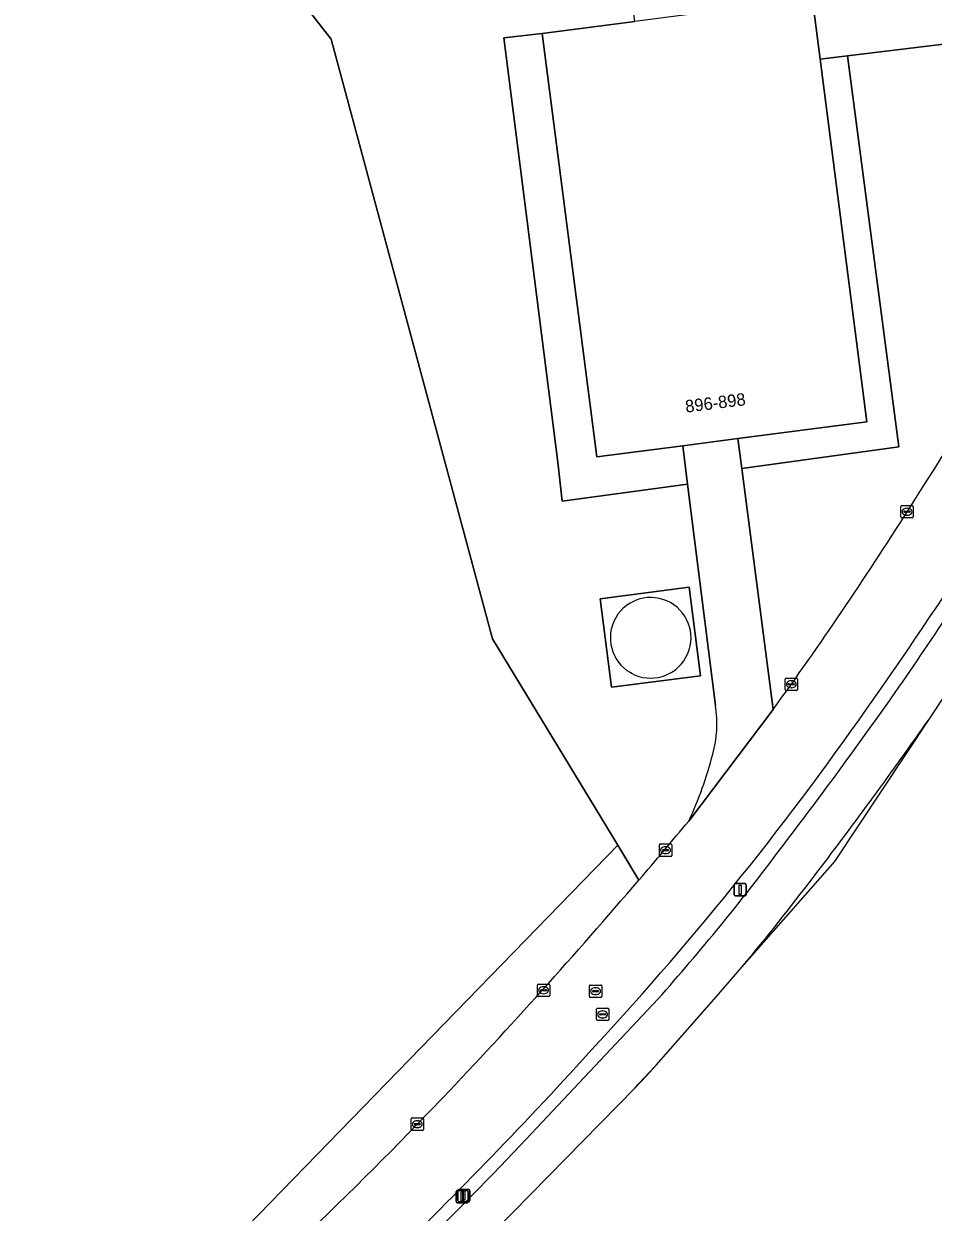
# Model space of a CAD drawing. Extents: x 154324 to 155744, y 382937 to 384188.
# Drawn here: x 155584 to 155657.6, y 383617.3 to 383713.4 of the extents above; entities that cross this region are included whole.
import ezdxf

# ---------------------------------------------------------------- set-up
doc = ezdxf.new("R2010")
doc.units = 0
for name, color, linetype in [('IMGEO_Berm_groen', 7, 'Continuous'), ('IMGEO_Fietspad_gesloten', 7, 'Continuous'), ('IMGEO_Groenvoorziening', 7, 'Continuous'), ('IMGEO_Kolk', 7, 'Continuous'), ('IMGEO_Lichtmast', 7, 'Continuous'), ('IMGEO_Loofbos', 7, 'Continuous'), ('IMGEO_Opslagtank', 7, 'Continuous'), ('IMGEO_Pand', 7, 'Continuous'), ('IMGEO_Pand_nummerreeks', 7, 'Continuous'), ('IMGEO_Rijbaan_lokaal_gesloten', 7, 'Continuous'), ('IMGEO_Rijbaan_lokaal_open', 7, 'Continuous'), ('IMGEO_Rioolput', 7, 'Continuous'), ('IMGEO_Voetpad_gesloten', 7, 'Continuous'), ('IMGEO_Voetpad_open', 7, 'Continuous')]:
    doc.layers.add(name, color=color, linetype=linetype)

msp = doc.modelspace()

# ---------------------------------------------------------------- linework, layer by layer
at = {"layer": 'IMGEO_Berm_groen'}
for points in [[(155633.769, 383644.126), (155632.059, 383646.947), (155597.437, 383611.327), (155576.794, 383595.659), (155549.768, 383579.161), (155547.779, 383587.369), (155534.763, 383581.234), (155533.851, 383571.452), (155530.121, 383566.643), (155490.655, 383546.367), (155461.561, 383535.514), (155441.996, 383529.835), (155428.359, 383526.353), (155427.323, 383530.623), (155422.919, 383530.383), (155423.075, 383528.299)], [(155622.542, 383620.967), (155624.644, 383623.181), (155635.323, 383634.523)], [(155615.853, 383624.392), (155617.913, 383626.51)]]:
    msp.add_lwpolyline(points, dxfattribs=at)
for centre, radius, start, end in [((155406.035, 383833.355), 302.23, 324.75564, 331.62534), ((155375.44, 383853.45), 339.952, 324.99586, 327.79438), ((155441.275, 383805.327), 257.289, 317.26147, 325.32443), ((155331.975, 383886.464), 394.498, 322.54614, 324.68943), ((155497.874, 383756.696), 183.898, 318.3674, 323.20947), ((155277.384, 383948.961), 468.971, 316.56195, 319.45788), ((155339.119, 383894.927), 393.142, 315.98882, 317.77462), ((155389.021, 383843.603), 315.446, 310.10044, 315.97887), ((155339.435, 383894.605), 392.69, 312.48719, 315.99059), ((155409.409, 383825.462), 295.371, 313.67122, 316.18495)]:
    msp.add_arc(centre, radius, start, end, dxfattribs=at)
at = {"layer": 'IMGEO_Fietspad_gesloten'}
for points in [[(155657.26, 383657.174), (155662.912, 383665.693), (155671.399, 383679.349)], [(155635.158, 383629.176), (155640.032, 383634.729), (155642.103, 383637.089)], [(155635.323, 383634.523), (155624.644, 383623.181), (155622.542, 383620.967)], [(155605.239, 383599.347), (155615.267, 383608.83), (155616.574, 383610.106), (155633.454, 383627.342)]]:
    msp.add_lwpolyline(points, dxfattribs=at)
for centre, radius, start, end in [((155375.44, 383853.45), 339.952, 324.99586, 327.79438), ((155331.975, 383886.464), 394.498, 322.54614, 324.68943), ((155477.346, 383785.966), 221.261, 324.2524, 324.40297), ((155348.365, 383873.286), 376.982, 322.60875, 324.93391), ((155497.874, 383756.696), 183.898, 318.3674, 323.20947), ((155477.39, 383773.839), 214.082, 320.2993, 322.78539), ((155294.776, 383943.672), 463.43, 316.95402, 317.26357), ((155409.409, 383825.462), 295.371, 313.67122, 316.18495)]:
    msp.add_arc(centre, radius, start, end, dxfattribs=at)
at = {"layer": 'IMGEO_Groenvoorziening'}
for points in [[(155625.95, 383712.576), (155633.448, 383713.544), (155632.159, 383723.491), (155631.753, 383723.439), (155628.142, 383722.972), (155621.591, 383773.488), (155589.41, 383766.825), (155588.986, 383764.634), (155584.778, 383742.905), (155608.878, 383712.126), (155621.944, 383663.636), (155632.059, 383646.947), (155633.769, 383644.126)], [(155670.387, 383713.18), (155650.638, 383710.777), (155654.779, 383679.151), (155642.087, 383677.42), (155644.632, 383657.932)], [(155639.962, 383658.245), (155637.712, 383676.149), (155627.569, 383674.769), (155627.219, 383677.909), (155622.843, 383712.235), (155625.95, 383712.576)], [(155642.103, 383637.089), (155649.6, 383645.629), (155657.26, 383657.174)], [(155633.454, 383627.342), (155634.359, 383628.266), (155635.158, 383629.176)]]:
    msp.add_lwpolyline(points, dxfattribs=at)
msp.add_lwpolyline([(155637.832, 383667.806), (155638.755, 383660.655), (155631.559, 383659.726), (155630.636, 383666.878)], close=True, dxfattribs=at)
for centre, radius, start, end in [((155439.555, 383814.512), 257.642, 326.92673, 334.31943), ((155410.012, 383828.426), 290.025, 323.99477, 327.80831), ((155630.953, 383656.773), 9.128, 344.27941, 9.27889), ((155477.346, 383785.966), 221.261, 324.2524, 324.40297), ((155348.365, 383873.286), 376.982, 322.60875, 324.93391), ((155608.776, 383662.395), 32.005, 335.0548, 345.34895), ((155274.541, 383951.344), 472.681, 319.46236, 320.21907), ((155477.39, 383773.839), 214.082, 320.2993, 322.78539), ((155294.776, 383943.672), 463.43, 316.95402, 317.26357)]:
    msp.add_arc(centre, radius, start, end, dxfattribs=at)
at = {"layer": 'IMGEO_Kolk'}
for p, q in [((155655.026, 383674.414), (155655.878, 383674.414)), ((155654.951, 383673.488), (155654.951, 383674.34)), ((155655.878, 383673.414), (155655.026, 383673.414)), ((155655.21, 383673.908), (155655.21, 383673.92)), ((155655.648, 383673.871), (155655.25, 383673.871)), ((155655.253, 383673.957), (155655.651, 383673.957)), ((155655.462, 383673.634), (155655.437, 383673.634)), ((155655.439, 383674.194), (155655.464, 383674.194)), ((155655.694, 383673.92), (155655.694, 383673.908)), ((155655.952, 383674.34), (155655.952, 383673.488)), ((155645.593, 383659.536), (155645.593, 383660.388)), ((155645.668, 383660.462), (155646.52, 383660.462)), ((155645.852, 383659.956), (155645.852, 383659.968)), ((155645.895, 383660.005), (155646.293, 383660.005)), ((155646.081, 383660.242), (155646.106, 383660.242)), ((155646.336, 383659.968), (155646.336, 383659.956)), ((155646.594, 383660.388), (155646.594, 383659.536)), ((155646.52, 383659.462), (155645.668, 383659.462)), ((155646.29, 383659.919), (155645.892, 383659.919)), ((155646.104, 383659.682), (155646.079, 383659.682)), ((155635.425, 383646.123), (155635.425, 383646.975)), ((155635.5, 383647.049), (155636.352, 383647.049)), ((155635.684, 383646.543), (155635.684, 383646.555)), ((155636.122, 383646.506), (155635.724, 383646.506)), ((155635.727, 383646.592), (155636.125, 383646.592)), ((155635.913, 383646.829), (155635.938, 383646.829)), ((155636.168, 383646.555), (155636.168, 383646.543)), ((155636.426, 383646.975), (155636.426, 383646.123)), ((155636.352, 383646.049), (155635.5, 383646.049)), ((155635.936, 383646.269), (155635.911, 383646.269)), ((155625.557, 383634.792), (155625.557, 383635.644)), ((155625.632, 383635.718), (155626.484, 383635.718)), ((155625.816, 383635.212), (155625.816, 383635.224)), ((155626.254, 383635.175), (155625.856, 383635.175)), ((155625.859, 383635.261), (155626.257, 383635.261)), ((155626.045, 383635.498), (155626.07, 383635.498)), ((155626.3, 383635.224), (155626.3, 383635.212)), ((155626.558, 383635.644), (155626.558, 383634.792)), ((155626.484, 383634.718), (155625.632, 383634.718)), ((155626.068, 383634.938), (155626.043, 383634.938)), ((155615.352, 383623.966), (155615.352, 383624.818)), ((155615.427, 383624.892), (155616.279, 383624.892)), ((155615.611, 383624.386), (155615.611, 383624.398)), ((155615.654, 383624.435), (155616.052, 383624.435)), ((155615.84, 383624.672), (155615.865, 383624.672)), ((155616.095, 383624.398), (155616.095, 383624.386)), ((155616.353, 383624.818), (155616.353, 383623.966)), ((155616.279, 383623.892), (155615.427, 383623.892)), ((155616.049, 383624.349), (155615.651, 383624.349)), ((155615.863, 383624.112), (155615.838, 383624.112))]:
    msp.add_line(p, q, dxfattribs=at)
for points in [[(155655.026, 383674.414), (155655.878, 383674.414)], [(155654.951, 383673.488), (155654.951, 383674.34)], [(155655.878, 383673.414), (155655.026, 383673.414)], [(155655.952, 383674.34), (155655.952, 383673.488)], [(155645.593, 383659.536), (155645.593, 383660.388)], [(155645.668, 383660.462), (155646.52, 383660.462)], [(155646.594, 383660.388), (155646.594, 383659.536)], [(155646.52, 383659.462), (155645.668, 383659.462)], [(155635.425, 383646.123), (155635.425, 383646.975)], [(155635.5, 383647.049), (155636.352, 383647.049)], [(155636.426, 383646.975), (155636.426, 383646.123)], [(155636.352, 383646.049), (155635.5, 383646.049)], [(155625.557, 383634.792), (155625.557, 383635.644)], [(155625.632, 383635.718), (155626.484, 383635.718)], [(155626.558, 383635.644), (155626.558, 383634.792)], [(155626.484, 383634.718), (155625.632, 383634.718)], [(155615.352, 383623.966), (155615.352, 383624.818)], [(155615.427, 383624.892), (155616.279, 383624.892)], [(155616.353, 383624.818), (155616.353, 383623.966)], [(155616.279, 383623.892), (155615.427, 383623.892)]]:
    msp.add_lwpolyline(points, dxfattribs=at)
for centre, radius, start, end in [((155655.028, 383674.338), 0.0765, 91.55205, 178.44795), ((155655.028, 383674.338), 0.0765, 91.55205, 178.44795), ((155655.876, 383674.338), 0.0765, 1.55205, 88.44795), ((155655.876, 383674.338), 0.0765, 1.55205, 88.44795), ((155655.028, 383673.49), 0.0765, 181.55205, 268.44795), ((155655.028, 383673.49), 0.0765, 181.55205, 268.44795), ((155655.25, 383673.917), 0.0403, 85.87752, 175.75265), ((155655.247, 383673.907), 0.0366, 178.93798, 274.71019), ((155655.651, 383673.914), 0.043, 264.86636, 352.45326), ((155655.655, 383673.919), 0.0386, 1.73085, 96.63898), ((155655.876, 383673.49), 0.0765, 271.55205, 358.44795), ((155655.876, 383673.49), 0.0765, 271.55205, 358.44795), ((155645.67, 383660.386), 0.0765, 91.55205, 178.44795), ((155645.67, 383660.386), 0.0765, 91.55205, 178.44795), ((155645.892, 383659.965), 0.0403, 85.87752, 175.75265), ((155645.889, 383659.955), 0.0366, 178.93798, 274.71019), ((155646.293, 383659.962), 0.043, 264.86636, 352.45326), ((155646.297, 383659.967), 0.0386, 1.73085, 96.63898), ((155646.518, 383660.386), 0.0765, 1.55205, 88.44795), ((155646.518, 383660.386), 0.0765, 1.55205, 88.44795), ((155645.67, 383659.538), 0.0765, 181.55205, 268.44795), ((155645.67, 383659.538), 0.0765, 181.55205, 268.44795), ((155646.518, 383659.538), 0.0765, 271.55205, 358.44795), ((155646.518, 383659.538), 0.0765, 271.55205, 358.44795), ((155635.502, 383646.973), 0.0765, 91.55205, 178.44795), ((155635.502, 383646.973), 0.0765, 91.55205, 178.44795), ((155635.724, 383646.552), 0.0403, 85.87752, 175.75265), ((155635.721, 383646.542), 0.0366, 178.93798, 274.71019), ((155636.125, 383646.549), 0.043, 264.86636, 352.45326), ((155636.129, 383646.554), 0.0386, 1.73085, 96.63898), ((155636.35, 383646.973), 0.0765, 1.55205, 88.44795), ((155636.35, 383646.973), 0.0765, 1.55205, 88.44795), ((155635.502, 383646.125), 0.0765, 181.55205, 268.44795), ((155635.502, 383646.125), 0.0765, 181.55205, 268.44795), ((155636.35, 383646.125), 0.0765, 271.55205, 358.44795), ((155636.35, 383646.125), 0.0765, 271.55205, 358.44795), ((155625.634, 383635.642), 0.0765, 91.55205, 178.44795), ((155625.634, 383635.642), 0.0765, 91.55205, 178.44795), ((155625.856, 383635.221), 0.0403, 85.87752, 175.75265), ((155625.853, 383635.211), 0.0366, 178.93798, 274.71019), ((155626.257, 383635.218), 0.043, 264.86636, 352.45326), ((155626.261, 383635.223), 0.0386, 1.73085, 96.63898), ((155626.482, 383635.642), 0.0765, 1.55205, 88.44795), ((155626.482, 383635.642), 0.0765, 1.55205, 88.44795), ((155625.634, 383634.794), 0.0765, 181.55205, 268.44795), ((155625.634, 383634.794), 0.0765, 181.55205, 268.44795), ((155626.482, 383634.794), 0.0765, 271.55205, 358.44795), ((155626.482, 383634.794), 0.0765, 271.55205, 358.44795), ((155615.429, 383624.816), 0.0765, 91.55205, 178.44795), ((155615.429, 383624.816), 0.0765, 91.55205, 178.44795), ((155615.651, 383624.395), 0.0403, 85.87752, 175.75265), ((155615.648, 383624.385), 0.0366, 178.93798, 274.71019), ((155616.052, 383624.392), 0.043, 264.86636, 352.45326), ((155616.056, 383624.397), 0.0386, 1.73085, 96.63898), ((155616.277, 383624.816), 0.0765, 1.55205, 88.44795), ((155616.277, 383624.816), 0.0765, 1.55205, 88.44795), ((155615.429, 383623.968), 0.0765, 181.55205, 268.44795), ((155615.429, 383623.968), 0.0765, 181.55205, 268.44795), ((155616.277, 383623.968), 0.0765, 271.55205, 358.44795), ((155616.277, 383623.968), 0.0765, 271.55205, 358.44795)]:
    msp.add_arc(centre, radius, start, end, dxfattribs=at)
for centre, major_axis, ratio, start_param, end_param in [((155655.438, 383673.914), (-0.387, 0.002), 0.722429, 4.712389, 7.853982), ((155655.463, 383673.914), (-0.39, 0.002), 0.717154, 1.570796, 4.712389), ((155646.08, 383659.962), (-0.387, 0.002), 0.722429, 4.712389, 7.853982), ((155646.105, 383659.962), (-0.39, 0.002), 0.717154, 1.570796, 4.712389), ((155635.912, 383646.549), (-0.387, 0.002), 0.722429, 4.712389, 7.853982), ((155635.937, 383646.549), (-0.39, 0.002), 0.717154, 1.570796, 4.712389), ((155626.044, 383635.218), (-0.387, 0.002), 0.722429, 4.712389, 7.853982), ((155626.069, 383635.218), (-0.39, 0.002), 0.717154, 1.570796, 4.712389), ((155615.839, 383624.392), (-0.387, 0.002), 0.722429, 4.712389, 7.853982), ((155615.864, 383624.392), (-0.39, 0.002), 0.717154, 1.570796, 4.712389)]:
    msp.add_ellipse(centre, major_axis=major_axis, ratio=ratio, start_param=start_param, end_param=end_param, dxfattribs=at)
at = {"layer": 'IMGEO_Lichtmast'}
for p, q in [((155641.465, 383642.948), (155641.465, 383643.748)), ((155641.465, 383643.748), (155641.465, 383642.948)), ((155641.565, 383643.848), (155642.355, 383643.848)), ((155642.355, 383643.848), (155641.565, 383643.848)), ((155642.455, 383643.748), (155642.455, 383642.948)), ((155642.455, 383642.948), (155642.455, 383643.748)), ((155642.355, 383642.848), (155641.565, 383642.848)), ((155641.565, 383642.848), (155642.355, 383642.848)), ((155618.981, 383618.139), (155618.981, 383618.939)), ((155618.981, 383618.939), (155618.981, 383618.139)), ((155619.081, 383619.039), (155619.871, 383619.039)), ((155619.871, 383619.039), (155619.081, 383619.039)), ((155619.118, 383618.214), (155619.118, 383619.014)), ((155619.118, 383619.014), (155619.118, 383618.214)), ((155619.218, 383619.114), (155620.008, 383619.114)), ((155620.008, 383619.114), (155619.218, 383619.114)), ((155619.971, 383618.939), (155619.971, 383618.139)), ((155619.971, 383618.139), (155619.971, 383618.939)), ((155620.108, 383619.014), (155620.108, 383618.214)), ((155620.108, 383618.214), (155620.108, 383619.014)), ((155619.871, 383618.039), (155619.081, 383618.039)), ((155619.081, 383618.039), (155619.871, 383618.039)), ((155620.008, 383618.114), (155619.218, 383618.114)), ((155619.218, 383618.114), (155620.008, 383618.114))]:
    msp.add_line(p, q, dxfattribs=at)
for points in [[(155641.885, 383643.723), (155642.035, 383643.723), (155642.035, 383642.973), (155641.885, 383642.973), (155641.885, 383643.723)], [(155619.401, 383618.914), (155619.551, 383618.914), (155619.551, 383618.164), (155619.401, 383618.164), (155619.401, 383618.914)], [(155619.538, 383618.989), (155619.688, 383618.989), (155619.688, 383618.239), (155619.538, 383618.239), (155619.538, 383618.989)]]:
    msp.add_lwpolyline(points, dxfattribs=at)
for centre, start, end in [((155641.565, 383643.748), 90, 180), ((155641.565, 383643.748), 90, 180), ((155642.355, 383643.748), 0, 90), ((155642.355, 383643.748), 360, 90), ((155641.565, 383642.948), 180, 270), ((155641.565, 383642.948), 180, 270), ((155642.355, 383642.948), 270, 0), ((155642.355, 383642.948), 270, 0), ((155619.081, 383618.939), 90, 180), ((155619.081, 383618.939), 90, 180), ((155619.218, 383619.014), 90, 180), ((155619.218, 383619.014), 90, 180), ((155619.871, 383618.939), 0, 90), ((155619.871, 383618.939), 360, 90), ((155620.008, 383619.014), 0, 90), ((155620.008, 383619.014), 360, 90), ((155619.081, 383618.139), 180, 270), ((155619.081, 383618.139), 180, 270), ((155619.218, 383618.214), 180, 270), ((155619.218, 383618.214), 180, 270), ((155619.871, 383618.139), 270, 0), ((155619.871, 383618.139), 270, 0), ((155620.008, 383618.214), 270, 0), ((155620.008, 383618.214), 270, 0)]:
    msp.add_arc(centre, 0.1, start, end, dxfattribs=at)
at = {"layer": 'IMGEO_Loofbos'}
for points in [[(155632.059, 383646.947), (155621.944, 383663.636), (155608.878, 383712.126), (155584.778, 383742.905), (155588.986, 383764.634), (155581.195, 383763.254), (155578.765, 383762.239), (155550.551, 383734.974), (155541.316, 383745.98), (155535.582, 383750.763), (155532.713, 383751.023), (155529.272, 383748.732), (155528.399, 383741.482), (155529.876, 383734.763), (155534.376, 383730.598), (155547.888, 383720.498), (155553.035, 383704.864), (155552.772, 383699.472), (155548.095, 383677.226), (155536.757, 383648.778), (155496.982, 383683.49)], [(155421.87, 383542.618), (155422.919, 383530.383), (155427.323, 383530.623), (155428.359, 383526.353), (155441.996, 383529.835), (155461.561, 383535.514), (155490.655, 383546.367), (155530.121, 383566.643), (155533.851, 383571.452), (155534.763, 383581.234), (155547.779, 383587.369), (155549.768, 383579.161), (155576.794, 383595.659), (155597.437, 383611.327), (155632.059, 383646.947)]]:
    msp.add_lwpolyline(points, dxfattribs=at)
at = {"layer": 'IMGEO_Opslagtank'}
msp.add_lwpolyline([(155633.081, 383660.904), (155633.17, 383660.854)], dxfattribs=at)
msp.add_arc((155634.722, 383663.721), 3.26, 241.5698, 239.77584, dxfattribs=at)
at = {"layer": 'IMGEO_Pand'}
msp.add_lwpolyline([(155630.369, 383678.354), (155637.322, 383679.252), (155641.773, 383679.827), (155652.207, 383681.174), (155648.42, 383710.507), (155647.881, 383714.683), (155647.789, 383715.395), (155636.969, 383713.998), (155633.448, 383713.544), (155625.95, 383712.576)], close=True, dxfattribs=at)
at = {"layer": 'IMGEO_Rijbaan_lokaal_gesloten'}
for points in [[(155644.632, 383657.932), (155637.795, 383648.897)], [(155617.913, 383626.51), (155615.853, 383624.392)]]:
    msp.add_lwpolyline(points, dxfattribs=at)
for centre, radius, start, end in [((155439.555, 383814.512), 257.642, 326.92673, 334.31943), ((155406.035, 383833.355), 302.23, 324.75564, 331.62534), ((155410.012, 383828.426), 290.025, 323.99477, 327.80831), ((155441.275, 383805.327), 257.289, 317.26147, 325.32443), ((155274.541, 383951.344), 472.681, 319.46236, 320.21907), ((155277.384, 383948.961), 468.971, 316.56195, 319.45788), ((155339.119, 383894.927), 393.142, 315.98882, 317.77462), ((155389.021, 383843.603), 315.446, 310.10044, 315.97887), ((155339.435, 383894.605), 392.69, 312.48719, 315.99059)]:
    msp.add_arc(centre, radius, start, end, dxfattribs=at)
at = {"layer": 'IMGEO_Rijbaan_lokaal_open'}
for points in [[(155673.679, 383717.816), (155654.149, 383715.41), (155652.941, 383715.27), (155647.881, 383714.683), (155648.42, 383710.507), (155650.638, 383710.777), (155670.387, 383713.18)], [(155642.087, 383677.42), (155641.773, 383679.827), (155637.322, 383679.252), (155637.712, 383676.149), (155639.962, 383658.245)], [(155637.795, 383648.897), (155644.632, 383657.932), (155642.087, 383677.42)]]:
    msp.add_lwpolyline(points, dxfattribs=at)
for centre, radius, start, end in [((155630.953, 383656.773), 9.128, 344.27941, 9.27889), ((155608.776, 383662.395), 32.005, 335.0548, 345.34895)]:
    msp.add_arc(centre, radius, start, end, dxfattribs=at)
at = {"layer": 'IMGEO_Rioolput'}
for p, q in [((155629.763, 383634.719), (155629.763, 383635.571)), ((155629.838, 383635.645), (155630.69, 383635.645)), ((155630.022, 383635.139), (155630.022, 383635.151)), ((155630.46, 383635.102), (155630.062, 383635.102)), ((155630.065, 383635.188), (155630.463, 383635.188)), ((155630.251, 383635.425), (155630.276, 383635.425)), ((155630.506, 383635.151), (155630.506, 383635.139)), ((155630.764, 383635.571), (155630.764, 383634.719)), ((155630.69, 383634.645), (155629.838, 383634.645)), ((155630.274, 383634.865), (155630.249, 383634.865)), ((155630.333, 383632.844), (155630.333, 383633.696)), ((155630.408, 383633.77), (155631.26, 383633.77)), ((155630.592, 383633.264), (155630.592, 383633.276)), ((155631.03, 383633.227), (155630.632, 383633.227)), ((155630.635, 383633.313), (155631.033, 383633.313)), ((155630.821, 383633.55), (155630.846, 383633.55)), ((155631.076, 383633.276), (155631.076, 383633.264)), ((155631.334, 383633.696), (155631.334, 383632.844)), ((155631.26, 383632.77), (155630.408, 383632.77)), ((155630.844, 383632.99), (155630.819, 383632.99))]:
    msp.add_line(p, q, dxfattribs=at)
for points in [[(155629.763, 383634.719), (155629.763, 383635.571)], [(155629.838, 383635.645), (155630.69, 383635.645)], [(155630.764, 383635.571), (155630.764, 383634.719)], [(155630.69, 383634.645), (155629.838, 383634.645)], [(155630.333, 383632.844), (155630.333, 383633.696)], [(155630.408, 383633.77), (155631.26, 383633.77)], [(155631.334, 383633.696), (155631.334, 383632.844)], [(155631.26, 383632.77), (155630.408, 383632.77)]]:
    msp.add_lwpolyline(points, dxfattribs=at)
for centre, radius, start, end in [((155629.84, 383635.569), 0.0765, 91.55205, 178.44795), ((155629.84, 383635.569), 0.0765, 91.55205, 178.44795), ((155630.062, 383635.148), 0.0403, 85.87752, 175.75265), ((155630.059, 383635.138), 0.0366, 178.93798, 274.71019), ((155630.463, 383635.145), 0.043, 264.86636, 352.45326), ((155630.467, 383635.15), 0.0386, 1.73085, 96.63898), ((155630.688, 383635.569), 0.0765, 1.55205, 88.44795), ((155630.688, 383635.569), 0.0765, 1.55205, 88.44795), ((155629.84, 383634.721), 0.0765, 181.55205, 268.44795), ((155629.84, 383634.721), 0.0765, 181.55205, 268.44795), ((155630.688, 383634.721), 0.0765, 271.55205, 358.44795), ((155630.688, 383634.721), 0.0765, 271.55205, 358.44795), ((155630.41, 383633.694), 0.0765, 91.55205, 178.44795), ((155630.41, 383633.694), 0.0765, 91.55205, 178.44795), ((155630.632, 383633.273), 0.0403, 85.87752, 175.75265), ((155630.629, 383633.263), 0.0366, 178.93798, 274.71019), ((155631.033, 383633.27), 0.043, 264.86636, 352.45326), ((155631.037, 383633.275), 0.0386, 1.73085, 96.63898), ((155631.258, 383633.694), 0.0765, 1.55205, 88.44795), ((155631.258, 383633.694), 0.0765, 1.55205, 88.44795), ((155630.41, 383632.846), 0.0765, 181.55205, 268.44795), ((155630.41, 383632.846), 0.0765, 181.55205, 268.44795), ((155631.258, 383632.846), 0.0765, 271.55205, 358.44795), ((155631.258, 383632.846), 0.0765, 271.55205, 358.44795)]:
    msp.add_arc(centre, radius, start, end, dxfattribs=at)
for centre, major_axis, ratio, start_param, end_param in [((155630.25, 383635.145), (-0.387, 0.002), 0.722429, 4.712389, 7.853982), ((155630.275, 383635.145), (-0.39, 0.002), 0.717154, 1.570796, 4.712389), ((155630.82, 383633.27), (-0.387, 0.002), 0.722429, 4.712389, 7.853982), ((155630.845, 383633.27), (-0.39, 0.002), 0.717154, 1.570796, 4.712389)]:
    msp.add_ellipse(centre, major_axis=major_axis, ratio=ratio, start_param=start_param, end_param=end_param, dxfattribs=at)
at = {"layer": 'IMGEO_Voetpad_gesloten'}
msp.add_lwpolyline([(155637.832, 383667.806), (155630.636, 383666.878), (155631.559, 383659.726), (155638.755, 383660.655)], close=True, dxfattribs=at)
msp.add_lwpolyline([(155633.17, 383660.854), (155633.081, 383660.904)], dxfattribs=at)
msp.add_arc((155634.722, 383663.721), 3.26, 241.5698, 239.77584, dxfattribs=at)
at = {"layer": 'IMGEO_Voetpad_open'}
for points in [[(155625.95, 383712.576), (155622.843, 383712.235), (155627.219, 383677.909), (155627.569, 383674.769), (155637.712, 383676.149), (155637.322, 383679.252), (155630.369, 383678.354)], [(155650.638, 383710.777), (155648.42, 383710.507), (155652.207, 383681.174), (155641.773, 383679.827), (155642.087, 383677.42), (155654.779, 383679.151)]]:
    msp.add_lwpolyline(points, close=True, dxfattribs=at)

# ---------------------------------------------------------------- texts
at = {"layer": 'IMGEO_Pand_nummerreeks'}
msp.add_text('896-898', height=1, rotation=7.12755, dxfattribs=at).set_placement((155637.579, 383681.925))

doc.saveas('drawing.dxf')
